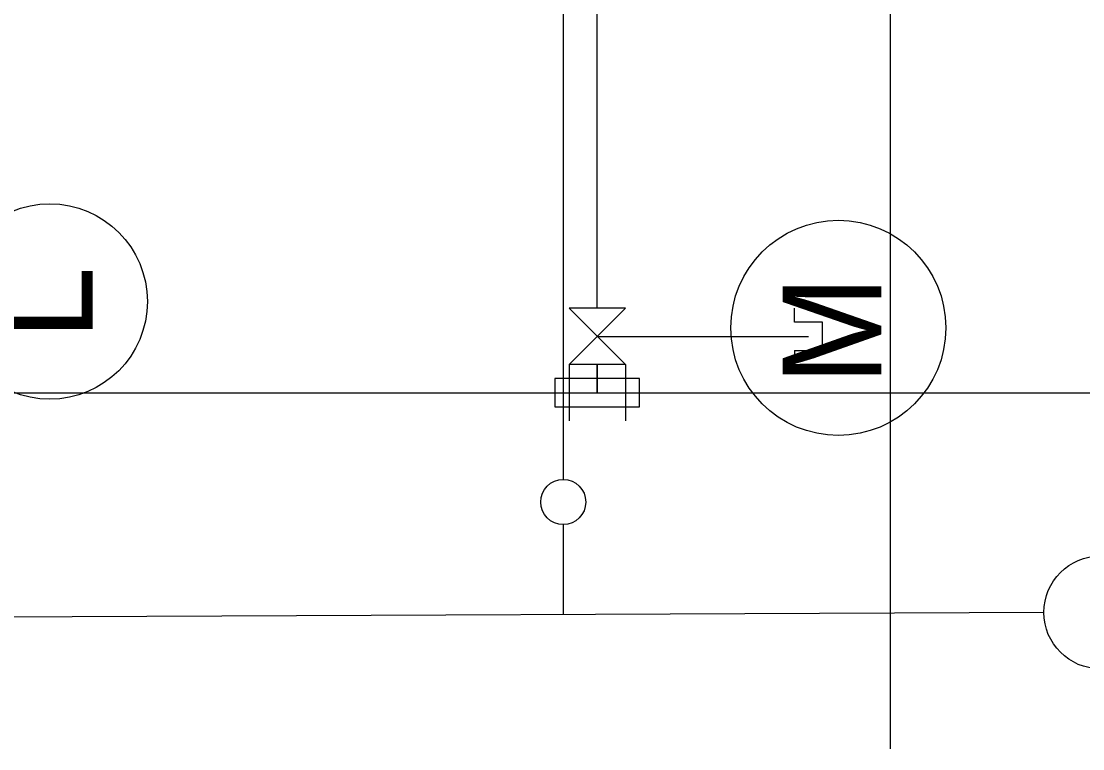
# Model space of a CAD drawing. Extents: x -264031 to -263588, y -1242281 to -1242059.
# Drawn here: x -263841.78 to -263832.36, y -1242253.3 to -1242246.84 of the extents above; entities that cross this region are included whole.
import ezdxf

# ---------------------------------------------------------------- set-up
doc = ezdxf.new("R2010")
doc.units = 0
for name, color, linetype in [('HESCON_OSI_STAVBY_KFA', 7, 'Continuous'), ('KFA_2D_SITUACIA_DSP', 7, 'Continuous'), ('KFA_JESTV_IS_DSP_-_KANAL_SPLASK', 7, 'Continuous')]:
    doc.layers.add(name, color=color, linetype=linetype)

msp = doc.modelspace()

# ---------------------------------------------------------------- linework, layer by layer
at = {"layer": 'HESCON_OSI_STAVBY_KFA'}
for centre, radius in [((-263841.5276, -1242249.3311), 0.867), ((-263834.5276, -1242249.5647), 0.9542)]:
    msp.add_circle(centre, radius, dxfattribs=at)
at = {"layer": 'KFA_2D_SITUACIA_DSP'}
for p, q in [((-263836.9678, -1242235.7572), (-263836.9691, -1242250.9091)), ((-263836.6677, -1242249.3899), (-263836.6678, -1242235.7572)), ((-263834.0678, -1242241.1322), (-263834.0678, -1242253.2979)), ((-263836.9178, -1242249.8899), (-263836.4177, -1242249.3899)), ((-263836.4177, -1242249.3899), (-263836.9177, -1242249.3899)), ((-263836.9177, -1242249.3899), (-263836.4178, -1242249.8899)), ((-263834.9178, -1242249.5149), (-263834.9178, -1242249.3899)), ((-263834.6678, -1242249.5148), (-263834.9178, -1242249.5149)), ((-263834.6678, -1242249.7648), (-263834.6678, -1242249.5148)), ((-263836.6678, -1242249.6399), (-263834.7928, -1242249.6398)), ((-263834.9178, -1242249.7649), (-263834.6678, -1242249.7648)), ((-263834.9178, -1242249.7649), (-263834.9178, -1242249.8899)), ((-263836.4178, -1242249.8899), (-263836.9178, -1242249.8899)), ((-263836.9178, -1242249.8899), (-263836.9178, -1242250.3899)), ((-263836.6678, -1242250.1399), (-263836.6678, -1242249.8899)), ((-263836.6678, -1242249.8899), (-263836.6678, -1242250.1399)), ((-263836.4178, -1242249.8899), (-263836.4178, -1242250.3899)), ((-263836.2928, -1242250.0149), (-263837.0428, -1242250.0149)), ((-263837.0428, -1242250.0149), (-263837.0428, -1242250.2649)), ((-263836.2928, -1242250.2649), (-263836.2928, -1242250.0149)), ((-263924.1428, -1242250.1399), (-263788.1428, -1242250.1399)), ((-263837.0428, -1242250.2649), (-263836.2928, -1242250.2649)), ((-263836.9692, -1242251.3091), (-263836.9692, -1242252.1091))]:
    msp.add_line(p, q, dxfattribs=at)
msp.add_circle((-263836.9692, -1242251.1091), 0.2, dxfattribs=at)
at = {"layer": 'KFA_JESTV_IS_DSP_-_KANAL_SPLASK'}
msp.add_line((-263832.7031, -1242252.0906), (-263876.5043, -1242252.2809), dxfattribs=at)
msp.add_circle((-263832.2031, -1242252.0884), 0.5, dxfattribs=at)

# ---------------------------------------------------------------- texts
at = {"layer": 'HESCON_OSI_STAVBY_KFA'}
for s, p in [('L', (-263841.147, -1242249.671)), ('M', (-263834.147, -1242250.0738))]:
    msp.add_text(s, height=0.875, rotation=90, dxfattribs=at).set_placement(p)

doc.saveas('drawing.dxf')
